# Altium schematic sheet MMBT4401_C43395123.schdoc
size 127 x 101 mm
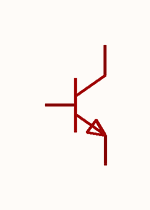
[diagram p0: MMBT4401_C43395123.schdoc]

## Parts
Q?  mmbt4401_c43395123  [SOT-23-3_L2.9-W1.3-P1.90-LS2.4-BR]  (value not drawn)

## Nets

Not connected (* = marked no-connect by the designer): Q? 1(B) 2(E) 3(C)

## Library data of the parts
Q? = mmbt4401_c43395123: 晶体管类型:NPN;集电极电流(Ic):600mA;集射极击穿电压(Vceo):40V;耗散功率(Pd):300mW;直流电流增益(hFE):300;; Manufacturer: CJ(江苏长电/长晶); AddInBom: yes; ModelId: c62791f0466c4ae2a892c056b845b0ca; ModelName: SOT-23-3P_L2.9-W1.3-H1.0-LS2.4-P0.95; ModelTransform: 98.425,114.173,0,180,0,0,0.0005,-0.0005,0; type: NPN; Current - Collector(Ic): 600mA; Collector - Emitter Voltage VCEO: 40V; Pd - Power Dissipation: 300mW; DC Current Gain: 300; Transition frequency(fT): 250MHz; Current - Collector Cutoff: 100nA; Vce Saturation(VCE(sat)): 400mV; Emitter-Base Voltage(Vebo): 6V; Number: 1个NPN; Configuration: 独立式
